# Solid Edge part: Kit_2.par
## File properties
Author: ahadarics
Last saved by: ahadarics
Revision: 76
Sűrűség: 0,000 kg/m^3
Pontosság: 0,990
Username: ahadarics
Dokumentum tartalom típus: 0
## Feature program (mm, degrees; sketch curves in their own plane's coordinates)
base feature "unnamed BaseFeature 1"
sketch for "Furat_1" plane through (0, 3, 12) normal (0, 0, 1) x-axis (0, 1, 0)
hole "Furat_1" diameter 9.728 finite  ThreadDepth = 7.5 mm
chamfer "Letörés_1" setback 0.7
sketch for "unnamed Protrusion 1" #1 plane through (0, 30.75, 0) normal (0, 1, 0) x-axis (0, 0, -1)
  line (-7.5498, -8) -> (7.5498, -8)
  arc centre (0, 0) radius 11 from (7.5498, -8) to (-7.5498, -8) cw
sketch for "unnamed Protrusion 1" #2 plane through (0, 30.75, 0) normal (0, 1, 0) x-axis (0, 0, -1)
  line (-7.5498, 8) -> (7.5498, 8)
extrude "unnamed Protrusion 1" add to key point along -normal
thread "unnamed Thread 1"
sketch for "Kivágás_1" #1 plane through (0, 30.75, 0) normal (0, 1, 0) x-axis (0, 0, -1)
  line (-7.5498, -8) -> (7.5498, -8)
  arc centre (0, 0) radius 11 from (7.5498, -8) to (-7.5498, -8) cw
sketch for "Kivágás_1" #2 plane through (0, 30.75, 0) normal (0, 1, 0) x-axis (0, 0, -1)
  line (-7.5498, 8) -> (7.5498, 8)
extrude "Kivágás_1" cut finite 16 along -normal
chamfer "Letörés_2" setback 1.5
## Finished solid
Body 1: solid body, 32 faces, 71 edges, 40 vertices.
  Faces by surface: plane 13, cylinder 11, cone 8
  Edges by curve: line 32, circle 31, intersection 4, spline 4
Bounding box of the edges (mm): 27.000 x 37.500 x 25.500, from (-13.5, -6.75, -13.5) to (13.5, 30.75, 12).
Cylindrical faces by radius (mm): R4 x1, R4.28 x1, R4.283 x1, R9.85 x2, R11 x4, R11.1 x1, R13.5 x1
Conical faces (half-angle, radius in mm at the cone's reference point): 45 deg R4.1 x2, 45 deg R4.983 x1, 45 deg R11 x2, 59 deg R2.1415 x1, 60 deg R10.425 x2
Planar faces by outward normal: +x 1, +y 7, +z 2, -x 1, -y 2
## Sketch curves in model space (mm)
arc centre (0, 30.75, 0) radius 11 from (8, 30.75, -7.5498) through (11, 30.75, 0) to (8, 30.75, 7.5498)
line (8, 30.75, 7.5498) -> (8, 30.75, -7.5498)
arc centre (0, 30.75, 0) radius 11 from (-8, 30.75, 7.5498) through (-11, 30.75, 0) to (-8, 30.75, -7.5498)
line (-8, 30.75, 7.5498) -> (-8, 30.75, -7.5498)
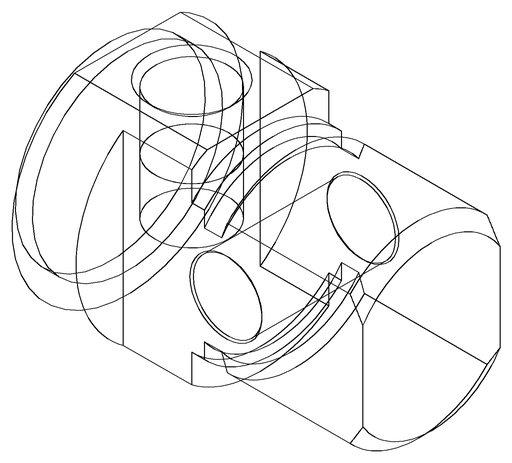
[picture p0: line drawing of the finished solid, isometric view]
